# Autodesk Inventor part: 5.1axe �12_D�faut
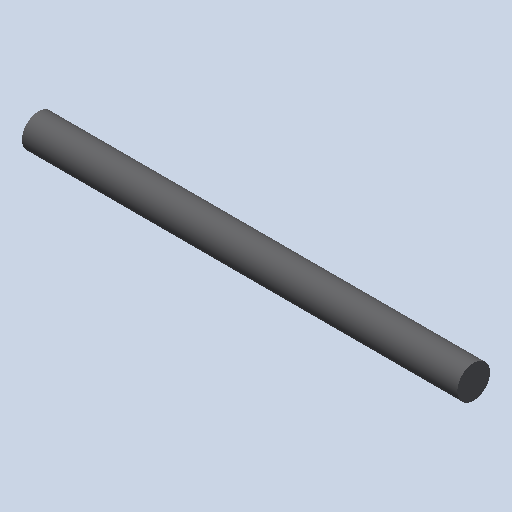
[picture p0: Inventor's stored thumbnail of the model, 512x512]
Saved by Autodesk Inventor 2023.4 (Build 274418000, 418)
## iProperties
Created: 2011-01
Part Number: 5.1axe �12_D�faut
Document SubType Name: Modeling
Designer: eric
Density: 1 g/cm^3
Mass: 17.9825 g
Surface Area: 62.2035 cm^2
Volume: 17.9825 cm^3
Material: Générique
Appearance: Yellow
Author: eric
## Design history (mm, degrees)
feature "Base1"
node "Corps solides"
node "Corps surfaciques"
node "Solide1"
